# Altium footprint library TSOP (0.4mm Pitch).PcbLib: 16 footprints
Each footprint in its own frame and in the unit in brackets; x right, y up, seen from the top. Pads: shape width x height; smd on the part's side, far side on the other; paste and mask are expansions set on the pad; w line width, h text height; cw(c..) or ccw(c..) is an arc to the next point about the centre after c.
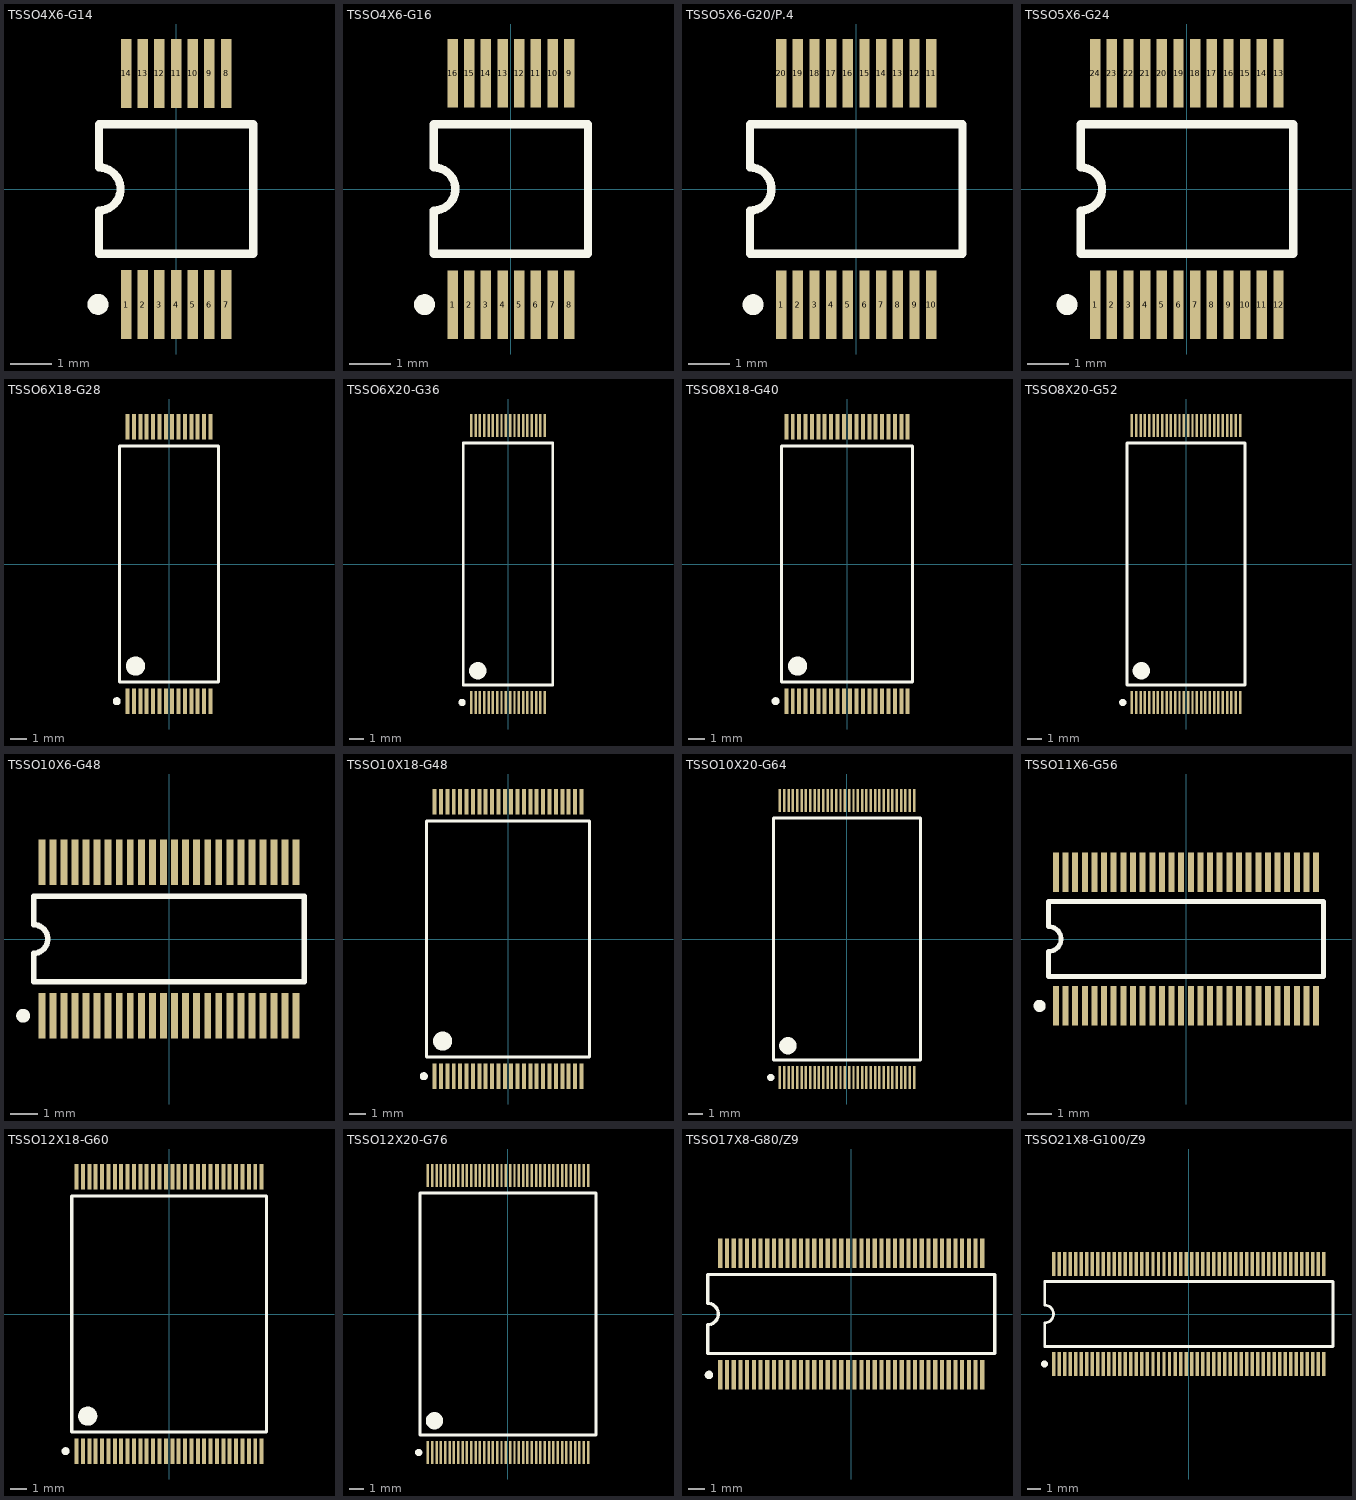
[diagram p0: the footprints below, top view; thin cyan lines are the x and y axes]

## TSSO4X6-G14 [mm]
pads (14):
  rect 0.25x1.65 smd: 1(-1.2,-2.775) 2(-0.8,-2.775) 3(-0.4,-2.775) 4(0,-2.775) 5(0.4,-2.775) 6(0.8,-2.775) 7(1.2,-2.775) 8(1.2,2.775) 9(0.8,2.775) 10(0.4,2.775) 11(0,2.775) 12(-0.4,2.775) 13(-0.8,2.775) 14(-1.2,2.775)
Top Overlay:
  circle w0.25: c-1.875,-2.769 r0.125
  lines w0.2: -1.85,-1.55 1.85,-1.55 1.85,1.55 -1.85,1.55 -1.85,0.517 cw(c-1.85,0) -1.85,-0.517 -1.85,-1.55

## TSSO4X6-G16 [mm]
pads (16):
  rect 0.25x1.65 smd: 1(-1.4,-2.775) 2(-1,-2.775) 3(-0.6,-2.775) 4(-0.2,-2.775) 5(0.2,-2.775) 6(0.6,-2.775) 7(1,-2.775) 8(1.4,-2.775) 9(1.4,2.775) 10(1,2.775) 11(0.6,2.775) 12(0.2,2.775) 13(-0.2,2.775) 14(-0.6,2.775) 15(-1,2.775) 16(-1.4,2.775)
Top Overlay:
  circle w0.25: c-2.075,-2.775 r0.125
  lines w0.2: -1.85,-1.55 -1.85,-0.517 ccw(c-1.85,0) -1.85,0.517 -1.85,1.55 1.85,1.55 1.85,-1.55 -1.85,-1.55

## TSSO5X6-G20/P.4 [mm]
pads (20):
  rect 0.25x1.65 smd: 1(-1.8,-2.775) 2(-1.4,-2.775) 3(-1,-2.775) 4(-0.6,-2.775) 5(-0.2,-2.775) 6(0.2,-2.775) 7(0.6,-2.775) 8(1,-2.775) 9(1.4,-2.775) 10(1.8,-2.775) 11(1.8,2.775) 12(1.4,2.775) 13(1,2.775) 14(0.6,2.775) 15(0.2,2.775) 16(-0.2,2.775) 17(-0.6,2.775) 18(-1,2.775) 19(-1.4,2.775) 20(-1.8,2.775)
Top Overlay:
  circle w0.25: c-2.475,-2.775 r0.125
  lines w0.2: -2.55,-1.55 -2.55,-0.517 ccw(c-2.55,0) -2.55,0.517 -2.55,1.55 2.55,1.55 2.55,-1.55 -2.55,-1.55

## TSSO5X6-G24 [mm]
pads (24):
  rect 0.25x1.65 smd: 1(-2.2,-2.775) 2(-1.8,-2.775) 3(-1.4,-2.775) 4(-1,-2.775) 5(-0.6,-2.775) 6(-0.2,-2.775) 7(0.2,-2.775) 8(0.6,-2.775) 9(1,-2.775) 10(1.4,-2.775) 11(1.8,-2.775) 12(2.2,-2.775) 13(2.2,2.775) 14(1.8,2.775) 15(1.4,2.775) 16(1,2.775) 17(0.6,2.775) 18(0.2,2.775) 19(-0.2,2.775) 20(-0.6,2.775) 21(-1,2.775) 22(-1.4,2.775) 23(-1.8,2.775) 24(-2.2,2.775)
Top Overlay:
  circle w0.25: c-2.875,-2.775 r0.125
  lines w0.2: -2.55,-1.55 2.55,-1.55 2.55,1.55 -2.55,1.55 -2.55,0.517 cw(c-2.55,0) -2.55,-0.517 -2.55,-1.55

## TSSO6X18-G28 [mm]
pads (28):
  rect 0.25x1.6 smd: 1(-2.6,-8.6) 2(-2.2,-8.6) 3(-1.8,-8.6) 4(-1.4,-8.6) 5(-1,-8.6) 6(-0.6,-8.6) 7(-0.2,-8.6) 8(0.2,-8.6) 9(0.6,-8.6) 10(1,-8.6) 11(1.4,-8.6) 12(1.8,-8.6) 13(2.2,-8.6) 14(2.6,-8.6) 15(2.6,8.6) 16(2.2,8.6) 17(1.8,8.6) 18(1.4,8.6) 19(1,8.6) 20(0.6,8.6) 21(0.2,8.6) 22(-0.2,8.6) 23(-0.6,8.6) 24(-1,8.6) 25(-1.4,8.6) 26(-1.8,8.6) 27(-2.2,8.6) 28(-2.6,8.6)
Top Overlay:
  circle w0.25: c-3.275,-8.6 r0.125
  circle w0.6: c-2.1,-6.4 r0.3
  lines w0.2: -3.1,-7.4 -3.1,-0.635 -3.1,7.4 3.1,7.4 3.1,-7.4 -3.1,-7.4

## TSSO6X20-G36 [mm]
pads (36):
  rect 0.17x1.6 smd: 1(-2.55,-9.6) 2(-2.25,-9.6) 3(-1.95,-9.6) 4(-1.65,-9.6) 5(-1.35,-9.6) 6(-1.05,-9.6) 7(-0.75,-9.6) 8(-0.45,-9.6) 9(-0.15,-9.6) 10(0.15,-9.6) 11(0.45,-9.6) 12(0.75,-9.6) 13(1.05,-9.6) 14(1.35,-9.6) 15(1.65,-9.6) 16(1.95,-9.6) 17(2.25,-9.6) 18(2.55,-9.6) 19(2.55,9.6) 20(2.25,9.6) 21(1.95,9.6) 22(1.65,9.6) 23(1.35,9.6) 24(1.05,9.6) 25(0.75,9.6) 26(0.45,9.6) 27(0.15,9.6) 28(-0.15,9.6) 29(-0.45,9.6) 30(-0.75,9.6) 31(-1.05,9.6) 32(-1.35,9.6) 33(-1.65,9.6) 34(-1.95,9.6) 35(-2.25,9.6) 36(-2.55,9.6)
Top Overlay:
  circle w0.6: c-2.1,-7.4 r0.3
  circle w0.25: c-3.185,-9.6 r0.125
  lines w0.2: -3.1,-8.4 3.1,-8.4 3.1,8.4 -3.1,8.4 -3.1,-0.635 -3.1,-8.4

## TSSO8X18-G40 [mm]
pads (40):
  rect 0.25x1.6 smd: 1(-3.8,-8.6) 2(-3.4,-8.6) 3(-3,-8.6) 4(-2.6,-8.6) 5(-2.2,-8.6) 6(-1.8,-8.6) 7(-1.4,-8.6) 8(-1,-8.6) 9(-0.6,-8.6) 10(-0.2,-8.6) 11(0.2,-8.6) 12(0.6,-8.6) 13(1,-8.6) 14(1.4,-8.6) 15(1.8,-8.6) 16(2.2,-8.6) 17(2.6,-8.6) 18(3,-8.6) 19(3.4,-8.6) 20(3.8,-8.6) 21(3.8,8.6) 22(3.4,8.6) 23(3,8.6) 24(2.6,8.6) 25(2.2,8.6) 26(1.8,8.6) 27(1.4,8.6) 28(1,8.6) 29(0.6,8.6) 30(0.2,8.6) 31(-0.2,8.6) 32(-0.6,8.6) 33(-1,8.6) 34(-1.4,8.6) 35(-1.8,8.6) 36(-2.2,8.6) 37(-2.6,8.6) 38(-3,8.6) 39(-3.4,8.6) 40(-3.8,8.6)
Top Overlay:
  circle w0.6: c-3.1,-6.4 r0.3
  circle w0.25: c-4.475,-8.6 r0.125
  lines w0.2: -4.1,-7.4 4.1,-7.4 4.1,7.4 -4.1,7.4 -4.1,-0.635 -4.1,-7.4

## TSSO8X20-G52 [mm]
pads (52):
  rect 0.17x1.6 smd: 1(-3.75,-9.6) 2(-3.45,-9.6) 3(-3.15,-9.6) 4(-2.85,-9.6) 5(-2.55,-9.6) 6(-2.25,-9.6) 7(-1.95,-9.6) 8(-1.65,-9.6) 9(-1.35,-9.6) 10(-1.05,-9.6) 11(-0.75,-9.6) 12(-0.45,-9.6) 13(-0.15,-9.6) 14(0.15,-9.6) 15(0.45,-9.6) 16(0.75,-9.6) 17(1.05,-9.6) 18(1.35,-9.6) 19(1.65,-9.6) 20(1.95,-9.6) 21(2.25,-9.6) 22(2.55,-9.6) 23(2.85,-9.6) 24(3.15,-9.6) 25(3.45,-9.6) 26(3.75,-9.6) 27(3.75,9.6) 28(3.45,9.6) 29(3.15,9.6) 30(2.85,9.6) 31(2.55,9.6) 32(2.25,9.6) 33(1.95,9.6) 34(1.65,9.6) 35(1.35,9.6) 36(1.05,9.6) 37(0.75,9.6) 38(0.45,9.6) 39(0.15,9.6) 40(-0.15,9.6) 41(-0.45,9.6) 42(-0.75,9.6) 43(-1.05,9.6) 44(-1.35,9.6) 45(-1.65,9.6) 46(-1.95,9.6) 47(-2.25,9.6) 48(-2.55,9.6) 49(-2.85,9.6) 50(-3.15,9.6) 51(-3.45,9.6) 52(-3.75,9.6)
Top Overlay:
  circle w0.25: c-4.385,-9.6 r0.125
  circle w0.6: c-3.1,-7.4 r0.3
  lines w0.2: -4.1,-8.4 -4.1,-0.635 -4.1,8.4 4.1,8.4 4.1,-8.4 -4.1,-8.4

## TSSO10X6-G48 [mm]
pads (48):
  rect 0.25x1.65 smd: 1(-4.6,-2.775) 2(-4.2,-2.775) 3(-3.8,-2.775) 4(-3.4,-2.775) 5(-3,-2.775) 6(-2.6,-2.775) 7(-2.2,-2.775) 8(-1.8,-2.775) 9(-1.4,-2.775) 10(-1,-2.775) 11(-0.6,-2.775) 12(-0.2,-2.775) 13(0.2,-2.775) 14(0.6,-2.775) 15(1,-2.775) 16(1.4,-2.775) 17(1.8,-2.775) 18(2.2,-2.775) 19(2.6,-2.775) 20(3,-2.775) 21(3.4,-2.775) 22(3.8,-2.775) 23(4.2,-2.775) 24(4.6,-2.775) 25(4.6,2.775) 26(4.2,2.775) 27(3.8,2.775) 28(3.4,2.775) 29(3,2.775) 30(2.6,2.775) 31(2.2,2.775) 32(1.8,2.775) 33(1.4,2.775) 34(1,2.775) 35(0.6,2.775) 36(0.2,2.775) 37(-0.2,2.775) 38(-0.6,2.775) 39(-1,2.775) 40(-1.4,2.775) 41(-1.8,2.775) 42(-2.2,2.775) 43(-2.6,2.775) 44(-3,2.775) 45(-3.4,2.775) 46(-3.8,2.775) 47(-4.2,2.775) 48(-4.6,2.775)
Top Overlay:
  circle w0.25: c-5.275,-2.775 r0.125
  lines w0.2: -4.9,-1.55 4.9,-1.55 4.9,1.55 -4.9,1.55 -4.9,0.517 cw(c-4.9,0) -4.9,-0.517 -4.9,-1.55

## TSSO10X18-G48 [mm]
pads (48):
  rect 0.25x1.6 smd: 1(-4.6,-8.6) 2(-4.2,-8.6) 3(-3.8,-8.6) 4(-3.4,-8.6) 5(-3,-8.6) 6(-2.6,-8.6) 7(-2.2,-8.6) 8(-1.8,-8.6) 9(-1.4,-8.6) 10(-1,-8.6) 11(-0.6,-8.6) 12(-0.2,-8.6) 13(0.2,-8.6) 14(0.6,-8.6) 15(1,-8.6) 16(1.4,-8.6) 17(1.8,-8.6) 18(2.2,-8.6) 19(2.6,-8.6) 20(3,-8.6) 21(3.4,-8.6) 22(3.8,-8.6) 23(4.2,-8.6) 24(4.6,-8.6) 25(4.6,8.6) 26(4.2,8.6) 27(3.8,8.6) 28(3.4,8.6) 29(3,8.6) 30(2.6,8.6) 31(2.2,8.6) 32(1.8,8.6) 33(1.4,8.6) 34(1,8.6) 35(0.6,8.6) 36(0.2,8.6) 37(-0.2,8.6) 38(-0.6,8.6) 39(-1,8.6) 40(-1.4,8.6) 41(-1.8,8.6) 42(-2.2,8.6) 43(-2.6,8.6) 44(-3,8.6) 45(-3.4,8.6) 46(-3.8,8.6) 47(-4.2,8.6) 48(-4.6,8.6)
Top Overlay:
  circle w0.6: c-4.1,-6.4 r0.3
  circle w0.25: c-5.275,-8.6 r0.125
  lines w0.2: -5.1,-7.4 5.1,-7.4 5.1,7.4 -5.1,7.4 -5.1,-0.635 -5.1,-7.4

## TSSO10X20-G64 [mm]
pads (64):
  rect 0.17x1.6 smd: 1(-4.65,-9.6) 2(-4.35,-9.6) 3(-4.05,-9.6) 4(-3.75,-9.6) 5(-3.45,-9.6) 6(-3.15,-9.6) 7(-2.85,-9.6) 8(-2.55,-9.6) 9(-2.25,-9.6) 10(-1.95,-9.6) 11(-1.65,-9.6) 12(-1.35,-9.6) 13(-1.05,-9.6) 14(-0.75,-9.6) 15(-0.45,-9.6) 16(-0.15,-9.6) 17(0.15,-9.6) 18(0.45,-9.6) 19(0.75,-9.6) 20(1.05,-9.6) 21(1.35,-9.6) 22(1.65,-9.6) 23(1.95,-9.6) 24(2.25,-9.6) 25(2.55,-9.6) 26(2.85,-9.6) 27(3.15,-9.6) 28(3.45,-9.6) 29(3.75,-9.6) 30(4.05,-9.6) 31(4.35,-9.6) 32(4.65,-9.6) 33(4.65,9.6) 34(4.35,9.6) 35(4.05,9.6) 36(3.75,9.6) 37(3.45,9.6) 38(3.15,9.6) 39(2.85,9.6) 40(2.55,9.6) 41(2.25,9.6) 42(1.95,9.6) 43(1.65,9.6) 44(1.35,9.6) 45(1.05,9.6) 46(0.75,9.6) 47(0.45,9.6) 48(0.15,9.6) 49(-0.15,9.6) 50(-0.45,9.6) 51(-0.75,9.6) 52(-1.05,9.6) 53(-1.35,9.6) 54(-1.65,9.6) 55(-1.95,9.6) 56(-2.25,9.6) 57(-2.55,9.6) 58(-2.85,9.6) 59(-3.15,9.6) 60(-3.45,9.6) 61(-3.75,9.6) 62(-4.05,9.6) 63(-4.35,9.6) 64(-4.65,9.6)
Top Overlay:
  circle w0.6: c-4.1,-7.4 r0.3
  circle w0.25: c-5.285,-9.6 r0.125
  lines w0.2: -5.1,-8.4 5.1,-8.4 5.1,8.4 -5.1,8.4 -5.1,-0.635 -5.1,-8.4

## TSSO11X6-G56 [mm]
pads (56):
  rect 0.25x1.65 smd: 1(-5.4,-2.775) 2(-5,-2.775) 3(-4.6,-2.775) 4(-4.2,-2.775) 5(-3.8,-2.775) 6(-3.4,-2.775) 7(-3,-2.775) 8(-2.6,-2.775) 9(-2.2,-2.775) 10(-1.8,-2.775) 11(-1.4,-2.775) 12(-1,-2.775) 13(-0.6,-2.775) 14(-0.2,-2.775) 15(0.2,-2.775) 16(0.6,-2.775) 17(1,-2.775) 18(1.4,-2.775) 19(1.8,-2.775) 20(2.2,-2.775) 21(2.6,-2.775) 22(3,-2.775) 23(3.4,-2.775) 24(3.8,-2.775) 25(4.2,-2.775) 26(4.6,-2.775) 27(5,-2.775) 28(5.4,-2.775) 29(5.4,2.775) 30(5,2.775) 31(4.6,2.775) 32(4.2,2.775) 33(3.8,2.775) 34(3.4,2.775) 35(3,2.775) 36(2.6,2.775) 37(2.2,2.775) 38(1.8,2.775) 39(1.4,2.775) 40(1,2.775) 41(0.6,2.775) 42(0.2,2.775) 43(-0.2,2.775) 44(-0.6,2.775) 45(-1,2.775) 46(-1.4,2.775) 47(-1.8,2.775) 48(-2.2,2.775) 49(-2.6,2.775) 50(-3,2.775) 51(-3.4,2.775) 52(-3.8,2.775) 53(-4.2,2.775) 54(-4.6,2.775) 55(-5,2.775) 56(-5.4,2.775)
Top Overlay:
  circle w0.25: c-6.075,-2.775 r0.125
  lines w0.2: -5.7,-1.55 5.7,-1.55 5.7,1.55 -5.7,1.55 -5.7,0.517 cw(c-5.7,0) -5.7,-0.517 -5.7,-1.55

## TSSO12X18-G60 [mm]
pads (60):
  rect 0.25x1.6 smd: 1(-5.8,-8.6) 2(-5.4,-8.6) 3(-5,-8.6) 4(-4.6,-8.6) 5(-4.2,-8.6) 6(-3.8,-8.6) 7(-3.4,-8.6) 8(-3,-8.6) 9(-2.6,-8.6) 10(-2.2,-8.6) 11(-1.8,-8.6) 12(-1.4,-8.6) 13(-1,-8.6) 14(-0.6,-8.6) 15(-0.2,-8.6) 16(0.2,-8.6) 17(0.6,-8.6) 18(1,-8.6) 19(1.4,-8.6) 20(1.8,-8.6) 21(2.2,-8.6) 22(2.6,-8.6) 23(3,-8.6) 24(3.4,-8.6) 25(3.8,-8.6) 26(4.2,-8.6) 27(4.6,-8.6) 28(5,-8.6) 29(5.4,-8.6) 30(5.8,-8.6) 31(5.8,8.6) 32(5.4,8.6) 33(5,8.6) 34(4.6,8.6) 35(4.2,8.6) 36(3.8,8.6) 37(3.4,8.6) 38(3,8.6) 39(2.6,8.6) 40(2.2,8.6) 41(1.8,8.6) 42(1.4,8.6) 43(1,8.6) 44(0.6,8.6) 45(0.2,8.6) 46(-0.2,8.6) 47(-0.6,8.6) 48(-1,8.6) 49(-1.4,8.6) 50(-1.8,8.6) 51(-2.2,8.6) 52(-2.6,8.6) 53(-3,8.6) 54(-3.4,8.6) 55(-3.8,8.6) 56(-4.2,8.6) 57(-4.6,8.6) 58(-5,8.6) 59(-5.4,8.6) 60(-5.8,8.6)
Top Overlay:
  circle w0.6: c-5.1,-6.4 r0.3
  circle w0.25: c-6.485,-8.6 r0.125
  lines w0.2: -6.1,-7.4 6.1,-7.4 6.1,7.4 -6.1,7.4 -6.1,-0.635 -6.1,-7.4

## TSSO12X20-G76 [mm]
pads (76):
  rect 0.17x1.6 smd: 1(-5.55,-9.6) 2(-5.25,-9.6) 3(-4.95,-9.6) 4(-4.65,-9.6) 5(-4.35,-9.6) 6(-4.05,-9.6) 7(-3.75,-9.6) 8(-3.45,-9.6) 9(-3.15,-9.6) 10(-2.85,-9.6) 11(-2.55,-9.6) 12(-2.25,-9.6) 13(-1.95,-9.6) 14(-1.65,-9.6) 15(-1.35,-9.6) 16(-1.05,-9.6) 17(-0.75,-9.6) 18(-0.45,-9.6) 19(-0.15,-9.6) 20(0.15,-9.6) 21(0.45,-9.6) 22(0.75,-9.6) 23(1.05,-9.6) 24(1.35,-9.6) 25(1.65,-9.6) 26(1.95,-9.6) 27(2.25,-9.6) 28(2.55,-9.6) 29(2.85,-9.6) 30(3.15,-9.6) 31(3.45,-9.6) 32(3.75,-9.6) 33(4.05,-9.6) 34(4.35,-9.6) 35(4.65,-9.6) 36(4.95,-9.6) 37(5.25,-9.6) 38(5.55,-9.6) 39(5.55,9.6) 40(5.25,9.6) 41(4.95,9.6) 42(4.65,9.6) 43(4.35,9.6) 44(4.05,9.6) 45(3.75,9.6) 46(3.45,9.6) 47(3.15,9.6) 48(2.85,9.6) 49(2.55,9.6) 50(2.25,9.6) 51(1.95,9.6) 52(1.65,9.6) 53(1.35,9.6) 54(1.05,9.6) 55(0.75,9.6) 56(0.45,9.6) 57(0.15,9.6) 58(-0.15,9.6) 59(-0.45,9.6) 60(-0.75,9.6) 61(-1.05,9.6) 62(-1.35,9.6) 63(-1.65,9.6) 64(-1.95,9.6) 65(-2.25,9.6) 66(-2.55,9.6) 67(-2.85,9.6) 68(-3.15,9.6) 69(-3.45,9.6) 70(-3.75,9.6) 71(-4.05,9.6) 72(-4.35,9.6) 73(-4.65,9.6) 74(-4.95,9.6) 75(-5.25,9.6) 76(-5.55,9.6)
Top Overlay:
  circle w0.25: c-6.195,-9.6 r0.125
  circle w0.6: c-5.1,-7.4 r0.3
  lines w0.2: -6.1,-8.4 -6.1,-0.635 -6.1,8.4 6.1,8.4 6.1,-8.4 -6.1,-8.4

## TSSO17X8-G80/Z9 [mm]
pads (80):
  rect 0.25x1.75 smd: 1(-7.8,-3.625) 2(-7.4,-3.625) 3(-7,-3.625) 4(-6.6,-3.625) 5(-6.2,-3.625) 6(-5.8,-3.625) 7(-5.4,-3.625) 8(-5,-3.625) 9(-4.6,-3.625) 10(-4.2,-3.625) 11(-3.8,-3.625) 12(-3.4,-3.625) 13(-3,-3.625) 14(-2.6,-3.625) 15(-2.2,-3.625) 16(-1.8,-3.625) 17(-1.4,-3.625) 18(-1,-3.625) 19(-0.6,-3.625) 20(-0.2,-3.625) 21(0.2,-3.625) 22(0.6,-3.625) 23(1,-3.625) 24(1.4,-3.625) 25(1.8,-3.625) 26(2.2,-3.625) 27(2.6,-3.625) 28(3,-3.625) 29(3.4,-3.625) 30(3.8,-3.625) 31(4.2,-3.625) 32(4.6,-3.625) 33(5,-3.625) 34(5.4,-3.625) 35(5.8,-3.625) 36(6.2,-3.625) 37(6.6,-3.625) 38(7,-3.625) 39(7.4,-3.625) 40(7.8,-3.625) 41(7.8,3.625) 42(7.4,3.625) 43(7,3.625) 44(6.6,3.625) 45(6.2,3.625) 46(5.8,3.625) 47(5.4,3.625) 48(5,3.625) 49(4.6,3.625) 50(4.2,3.625) 51(3.8,3.625) 52(3.4,3.625) 53(3,3.625) 54(2.6,3.625) 55(2.2,3.625) 56(1.8,3.625) 57(1.4,3.625) 58(1,3.625) 59(0.6,3.625) 60(0.2,3.625) 61(-0.2,3.625) 62(-0.6,3.625) 63(-1,3.625) 64(-1.4,3.625) 65(-1.8,3.625) 66(-2.2,3.625) 67(-2.6,3.625) 68(-3,3.625) 69(-3.4,3.625) 70(-3.8,3.625) 71(-4.2,3.625) 72(-4.6,3.625) 73(-5,3.625) 74(-5.4,3.625) 75(-5.8,3.625) 76(-6.2,3.625) 77(-6.6,3.625) 78(-7,3.625) 79(-7.4,3.625) 80(-7.8,3.625)
Top Overlay:
  circle w0.25: c-8.475,-3.625 r0.125
  lines w0.2: -8.55,-2.35 -8.55,-0.635 ccw(c-8.55,0) -8.55,0.635 -8.55,2.35 8.55,2.35 8.55,-2.35 -8.55,-2.35

## TSSO21X8-G100/Z9 [mm]
pads (100):
  rect 0.25x1.75 smd: 1(-9.8,-3.625) 2(-9.4,-3.625) 3(-9,-3.625) 4(-8.6,-3.625) 5(-8.2,-3.625) 6(-7.8,-3.625) 7(-7.4,-3.625) 8(-7,-3.625) 9(-6.6,-3.625) 10(-6.2,-3.625) 11(-5.8,-3.625) 12(-5.4,-3.625) 13(-5,-3.625) 14(-4.6,-3.625) 15(-4.2,-3.625) 16(-3.8,-3.625) 17(-3.4,-3.625) 18(-3,-3.625) 19(-2.6,-3.625) 20(-2.2,-3.625) 21(-1.8,-3.625) 22(-1.4,-3.625) 23(-1,-3.625) 24(-0.6,-3.625) 25(-0.2,-3.625) 26(0.2,-3.625) 27(0.6,-3.625) 28(1,-3.625) 29(1.4,-3.625) 30(1.8,-3.625) 31(2.2,-3.625) 32(2.6,-3.625) 33(3,-3.625) 34(3.4,-3.625) 35(3.8,-3.625) 36(4.2,-3.625) 37(4.6,-3.625) 38(5,-3.625) 39(5.4,-3.625) 40(5.8,-3.625) 41(6.2,-3.625) 42(6.6,-3.625) 43(7,-3.625) 44(7.4,-3.625) 45(7.8,-3.625) 46(8.2,-3.625) 47(8.6,-3.625) 48(9,-3.625) 49(9.4,-3.625) 50(9.8,-3.625) 51(9.8,3.625) 52(9.4,3.625) 53(9,3.625) 54(8.6,3.625) 55(8.2,3.625) 56(7.8,3.625) 57(7.4,3.625) 58(7,3.625) 59(6.6,3.625) 60(6.2,3.625) 61(5.8,3.625) 62(5.4,3.625) 63(5,3.625) 64(4.6,3.625) 65(4.2,3.625) 66(3.8,3.625) 67(3.4,3.625) 68(3,3.625) 69(2.6,3.625) 70(2.2,3.625) 71(1.8,3.625) 72(1.4,3.625) 73(1,3.625) 74(0.6,3.625) 75(0.2,3.625) 76(-0.2,3.625) 77(-0.6,3.625) 78(-1,3.625) 79(-1.4,3.625) 80(-1.8,3.625) 81(-2.2,3.625) 82(-2.6,3.625) 83(-3,3.625) 84(-3.4,3.625) 85(-3.8,3.625) 86(-4.2,3.625) 87(-4.6,3.625) 88(-5,3.625) 89(-5.4,3.625) 90(-5.8,3.625) 91(-6.2,3.625) 92(-6.6,3.625) 93(-7,3.625) 94(-7.4,3.625) 95(-7.8,3.625) 96(-8.2,3.625) 97(-8.6,3.625) 98(-9,3.625) 99(-9.4,3.625) 100(-9.8,3.625)
Top Overlay:
  circle w0.25: c-10.475,-3.625 r0.125
  lines w0.2: -10.45,-2.35 -10.45,-0.635 ccw(c-10.45,0) -10.45,0.635 -10.45,2.35 10.45,2.35 10.45,-2.35 -10.45,-2.35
